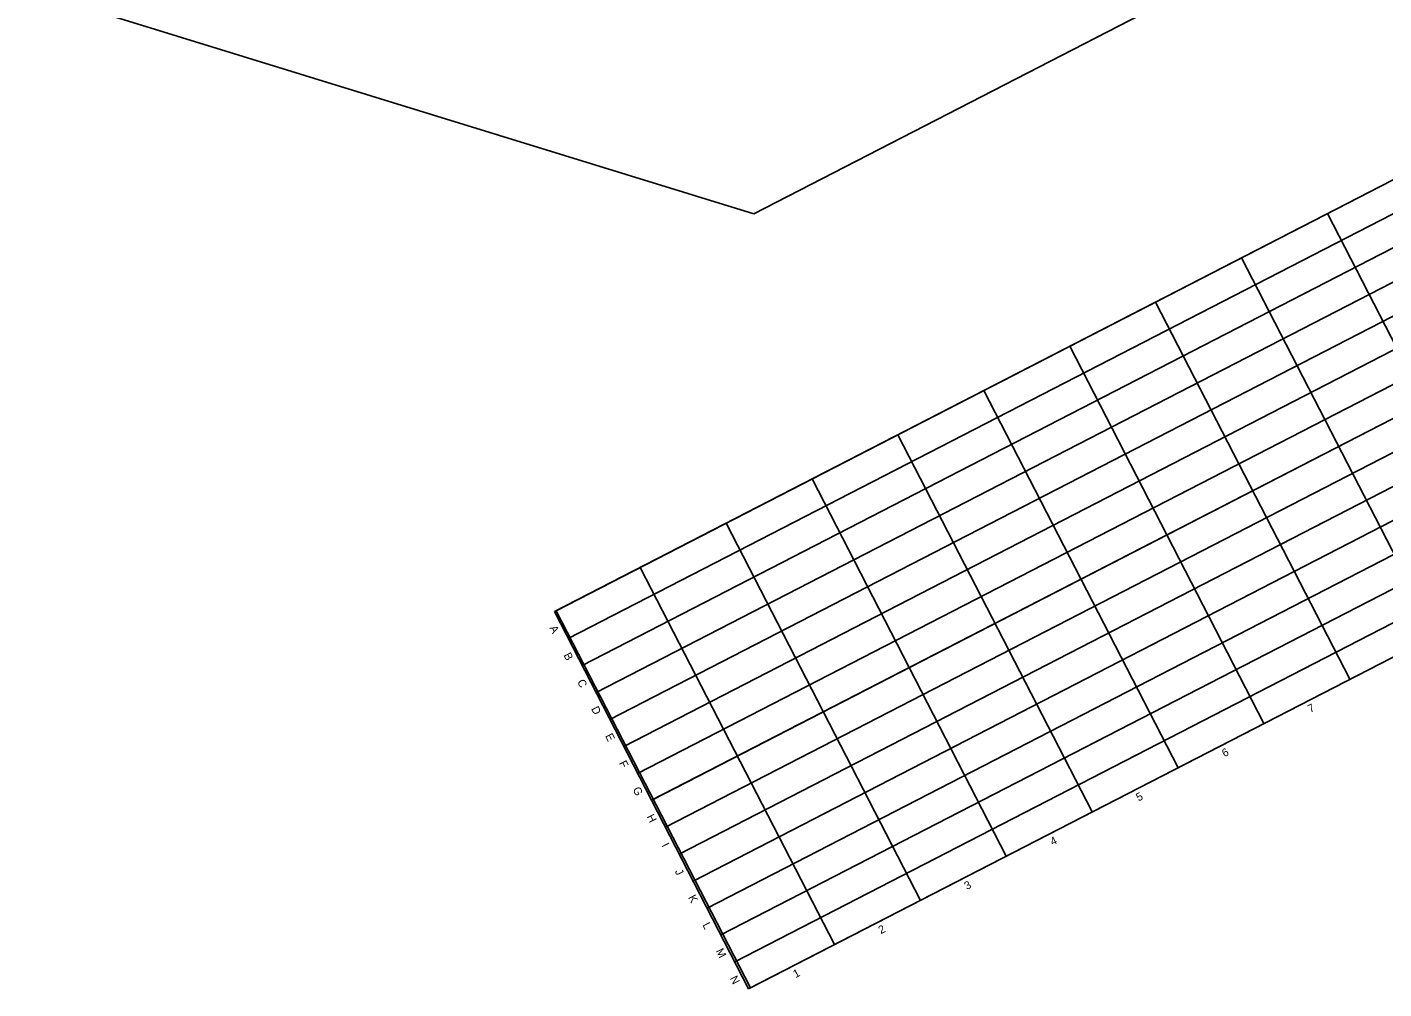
# Model space of a CAD drawing. Extents: x -886320 to -884760, y -1024172 to -1023483.
# Drawn here: x -886095.8 to -885926.3, y -1024171.6 to -1024051.4 of the extents above; entities that cross this region are included whole.
import ezdxf

# ---------------------------------------------------------------- set-up
doc = ezdxf.new("R2010")
doc.units = 0
for name, color, linetype in [('AGA__Netisknout', 7, 'Continuous'), ('Stavajici_betonova_draha', 7, 'Continuous'), ('Stavajici_betonova_draha_osa', 7, 'Continuous'), ('Stavajici_betonova_draha_Popis desky', 7, 'Continuous'), ('Stavajici_betonova_draha_Spára', 7, 'Continuous'), ('Stavajici_drahovy_system', 7, 'Continuous')]:
    doc.layers.add(name, color=color, linetype=linetype)

msp = doc.modelspace()

# ---------------------------------------------------------------- linework, layer by layer
at = {"layer": 'AGA__Netisknout'}
msp.add_line((-886017.78, -1024147.99), (-884773.13, -1023507.02), dxfattribs=at)
at = {"layer": 'Stavajici_betonova_draha'}
for p, q in [((-886029.69, -1024124.32), (-884785.04, -1023483.35)), ((-886029.69, -1024124.32), (-884785.04, -1023483.35)), ((-886005.42, -1024171.44), (-884760.77, -1023530.47)), ((-886005.42, -1024171.44), (-884760.77, -1023530.47)), ((-886029.69, -1024124.32), (-886005.42, -1024171.44)), ((-886029.69, -1024124.32), (-886005.42, -1024171.44))]:
    msp.add_line(p, q, dxfattribs=at)
at = {"layer": 'Stavajici_betonova_draha_osa'}
msp.add_line((-886017.55, -1024147.88), (-884772.9, -1023506.91), dxfattribs=at)
at = {"layer": 'Stavajici_betonova_draha_Spára'}
for p, q in [((-886029.91, -1024124.43), (-884785.26, -1023483.46)), ((-886028.18, -1024127.8), (-884783.53, -1023486.82)), ((-886026.44, -1024131.16), (-884781.79, -1023490.19)), ((-886024.71, -1024134.53), (-884780.06, -1023493.56)), ((-886022.98, -1024137.89), (-884778.33, -1023496.92)), ((-886021.24, -1024141.26), (-884776.59, -1023500.29)), ((-886019.51, -1024144.63), (-884774.86, -1023503.65)), ((-886016.04, -1024151.36), (-884771.39, -1023510.39)), ((-886014.31, -1024154.72), (-884769.66, -1023513.75)), ((-886012.58, -1024158.09), (-884767.93, -1023517.12)), ((-886010.84, -1024161.46), (-884766.19, -1023520.48)), ((-886009.11, -1024164.82), (-884764.46, -1023523.85)), ((-886007.38, -1024168.19), (-884762.73, -1023527.21)), ((-886005.64, -1024171.55), (-884760.99, -1023530.58)), ((-885933.34, -1024074.7), (-885909.07, -1024121.82)), ((-885944.07, -1024080.23), (-885919.8, -1024127.35)), ((-885954.8, -1024085.75), (-885930.53, -1024132.87)), ((-885965.53, -1024091.28), (-885941.26, -1024138.4)), ((-885976.26, -1024096.8), (-885951.99, -1024143.92)), ((-885986.99, -1024102.33), (-885962.72, -1024149.45)), ((-885997.72, -1024107.85), (-885973.45, -1024154.98)), ((-886008.45, -1024113.38), (-885984.18, -1024160.5)), ((-886019.18, -1024118.9), (-885994.91, -1024166.03)), ((-886029.91, -1024124.43), (-886005.64, -1024171.55))]:
    msp.add_line(p, q, dxfattribs=at)
at = {"layer": 'Stavajici_drahovy_system'}
for p, q in [((-886005.01, -1024074.75), (-885927.49, -1024034.82)), ((-886095.78, -1024046.74), (-886005.01, -1024074.75))]:
    msp.add_line(p, q, dxfattribs=at)

# ---------------------------------------------------------------- texts
at = {"layer": 'Stavajici_betonova_draha_Popis desky'}
for s, rotation, p in [('A', 297.2477, (-886030.55, -1024126.46)), ('B', 297.2477, (-886028.8, -1024129.85)), ('C', 297.2477, (-886027.09, -1024133.19)), ('D', 297.2477, (-886025.35, -1024136.56)), ('7', 27.2477, (-885935.47, -1024137.1)), ('E', 297.2477, (-886023.6, -1024139.95)), ('6', 27.2477, (-885946.2, -1024142.63)), ('F', 297.2477, (-886021.86, -1024143.34)), ('G', 297.2477, (-886020.16, -1024146.63)), ('5', 27.2477, (-885956.93, -1024148.16)), ('H', 297.2477, (-886018.41, -1024150.04)), ('I', 297.2477, (-886016.56, -1024153.63)), ('4', 27.2477, (-885967.66, -1024153.68)), ('J', 297.2477, (-886014.89, -1024156.88)), ('3', 27.2477, (-885978.39, -1024159.21)), ('K', 297.2477, (-886013.22, -1024160.12)), ('L', 297.2477, (-886011.44, -1024163.56)), ('2', 27.2477, (-885989.12, -1024164.73)), ('M', 297.2477, (-886009.77, -1024166.81)), ('1', 27.2477, (-885999.78, -1024170.22)), ('N', 297.2477, (-886008.01, -1024170.23))]:
    msp.add_text(s, height=1, rotation=rotation, dxfattribs=at).set_placement(p)

doc.saveas('drawing.dxf')
